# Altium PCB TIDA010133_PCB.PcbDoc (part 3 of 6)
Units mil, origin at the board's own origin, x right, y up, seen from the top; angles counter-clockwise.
Board outline 4100 x 6400 mil, 8 copper layers (Top Layer, Ground 1, Signal 1, Power 1, Ground 2, Signal 2, Power 2, Bottom Layer), stack 60.4 mil thick; 587 components, 322 nets, 1661 pads, 859 vias.
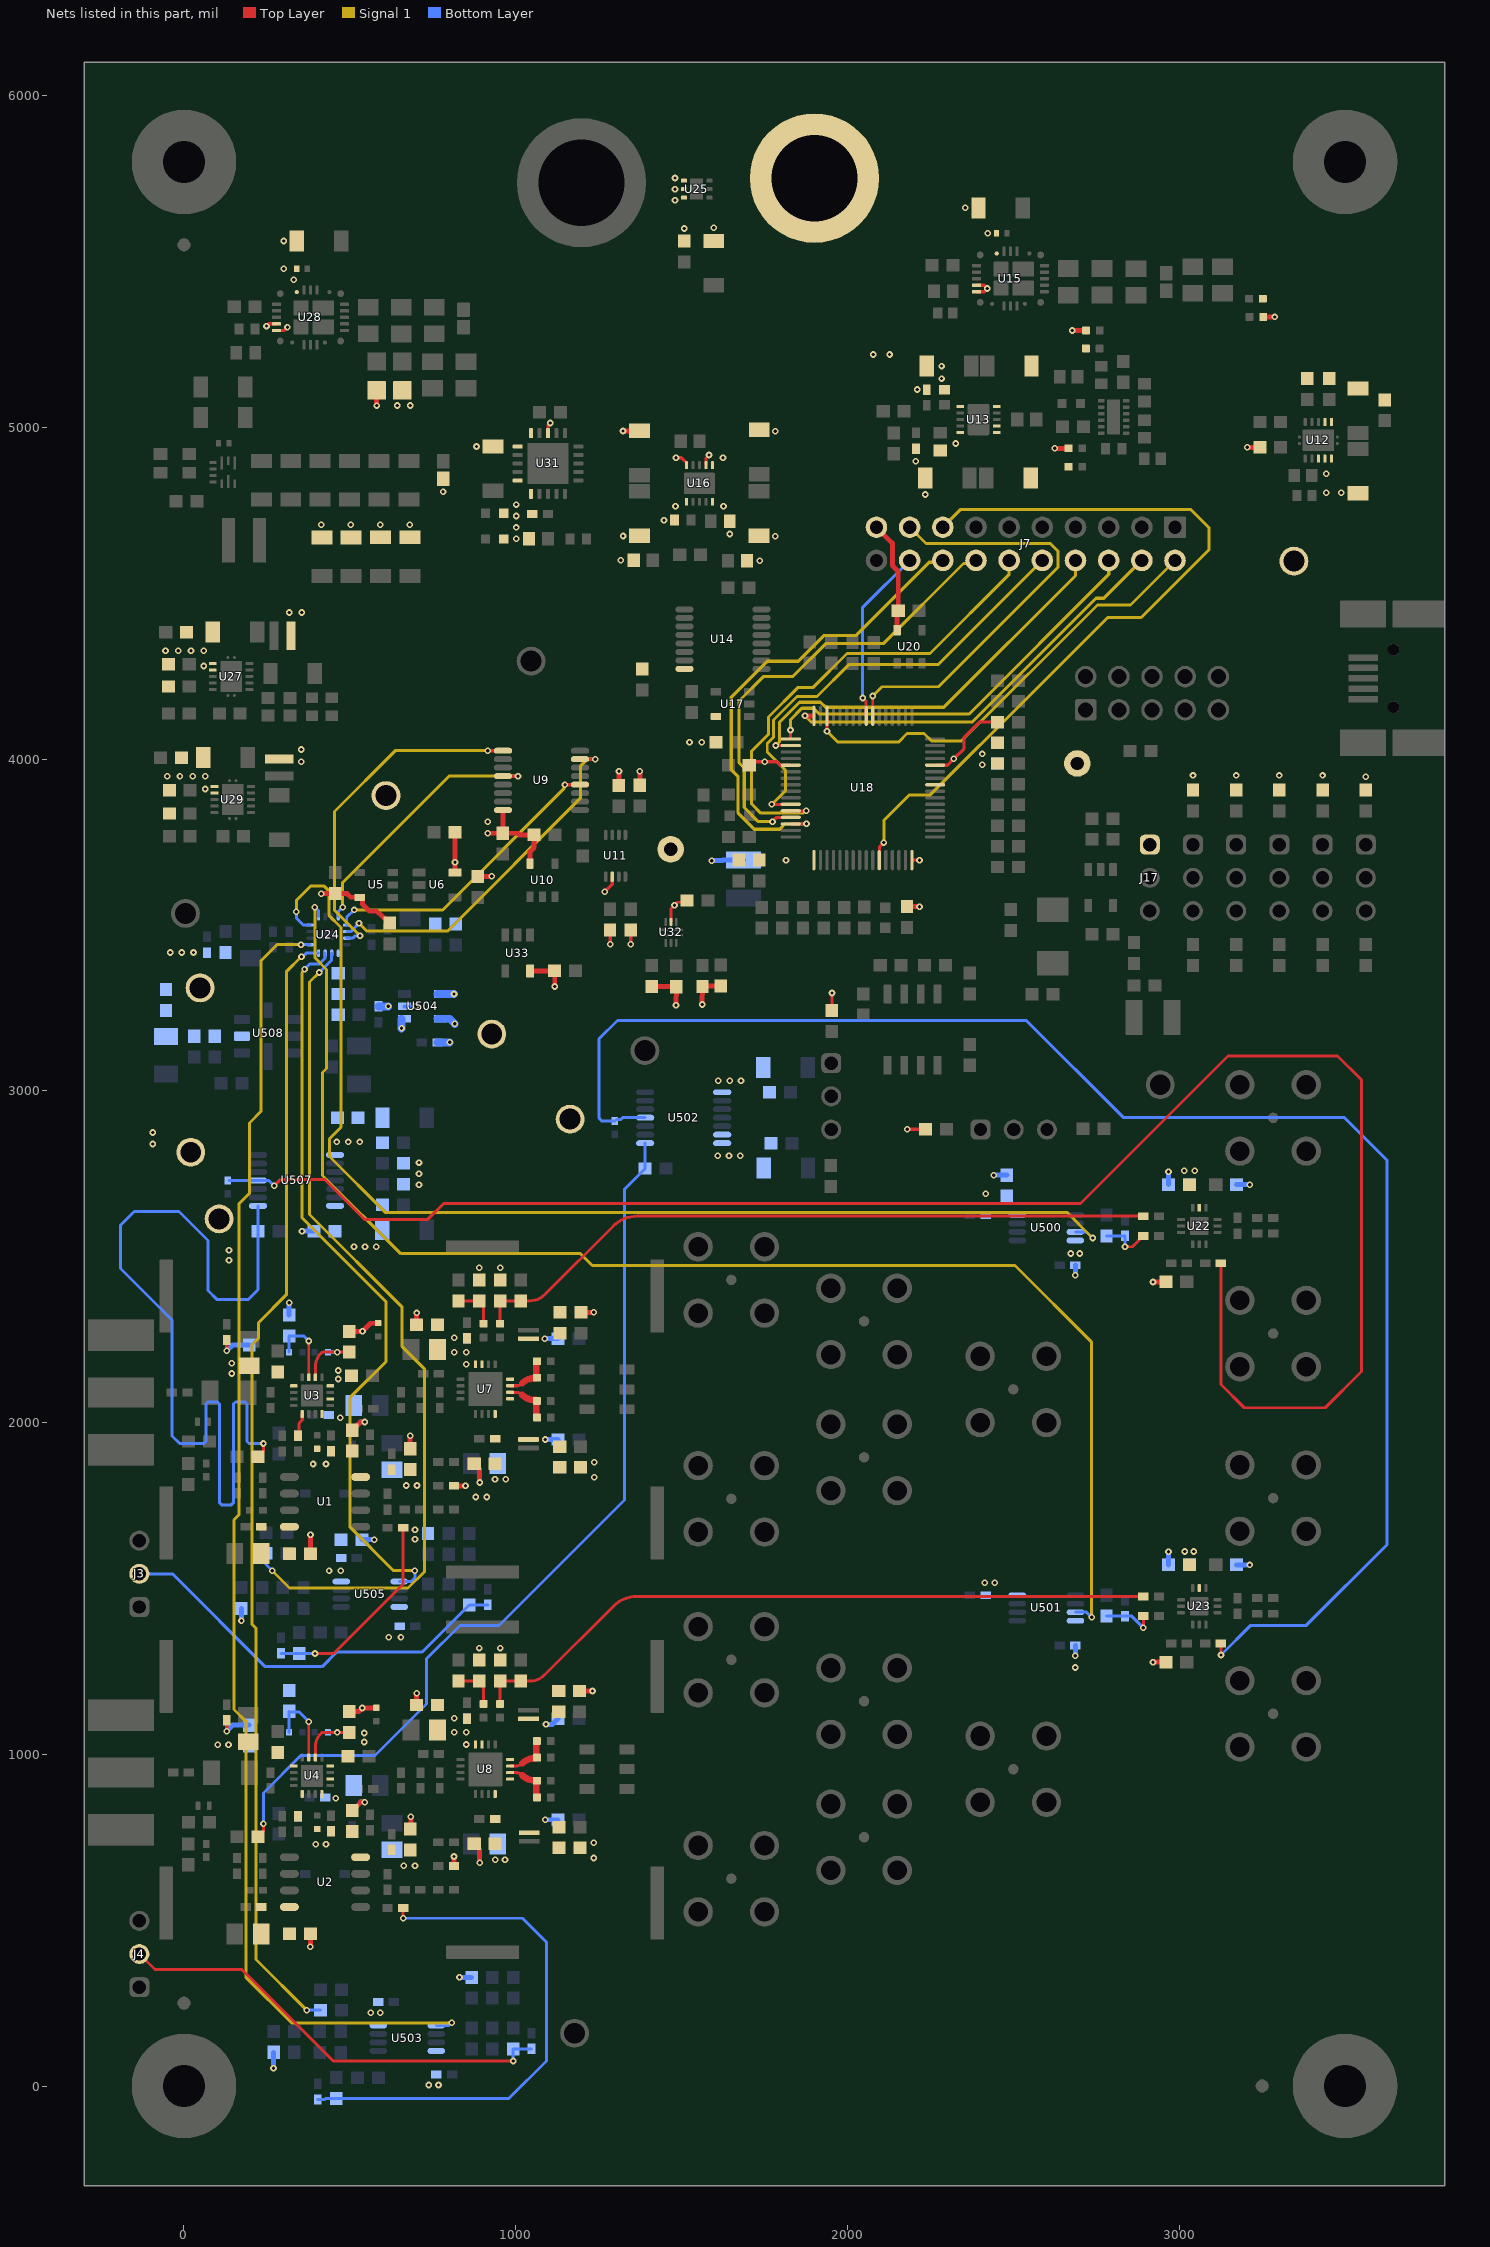
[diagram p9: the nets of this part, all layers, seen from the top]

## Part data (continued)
R101 R167: library part CMP-0090334-1, "6 mOhms ±1% 1W Chip Resistor Wide 0805 (2012 Metric), 0508 Automotive AEC-Q200, Current Sense Metal Foil", Digikey Part Number=408-1596-1-ND, Manufacturer=Susumu, Mouser Part Number=754-KRL2012EMR006FT5, Operating Temperature Range="-55°C to +155°C", Power_W=660mW, TempCo=50ppm/°C, Tolerance_%=1%
R103: library part CMP-2000-00576-1, "57.6 kOhms ±1% 0.1W, 1/10W Chip Resistor 0603 (1608 Metric) Automotive AEC-Q200 Thick Film", Manufacturer=Panasonic
R108: library part CMP-1012-00672-2, "28 kOhms ±1% 0.1W, 1/10W Chip Resistor 0603 (1608 Metric) Automotive AEC-Q200 Thick Film", Manufacturer=Panasonic
R110 R134: library part CMP-0025765-4, "RES, 270, 5%, 0.1 W, AEC-Q200 Grade 0, 0603", Manufacturer=Vishay-Dale, Power_W=100mW, Supplier Part Number 1=541-270GCT-ND, TempCo="200 ppm/C", Tolerance_%=5%, Value2=0.1W, Value_Code=270R, ValueDisplayed=270
R113 R114: library part CMP-0096818-1, "0 Ohms Jumper 0.245W Chip Resistor 0805 (2012 Metric) - Metal Element", Digikey Part Number=JR0805X35ECT-ND, Manufacturer=Ohmite, Mouser Part Number=588-JR0805X35E, Operating Temperature Range="-55°C to +150°C", Power_W=245mW
R116 R117: library part CMP-2000-00441-1, "33.2 kOhms ±1% 0.1W, 1/10W Chip Resistor 0603 (1608 Metric) Automotive AEC-Q200 Thick Film", Manufacturer=Panasonic
R133: library part CMP-0025769-4, "RES, 2.2 k, 5%, 0.1 W, AEC-Q200 Grade 0, 0603", Manufacturer=Vishay-Dale, Power_W=100mW, Supplier Part Number 1=541-2.2KGCT-ND, TempCo="200 ppm/C", Tolerance_%=5%, Value2=0.1W, Value_Code=2k20, ValueDisplayed=2.2k
R137 R138: library part CMP-0022004-4, "RES, 10.0, 1%, 0.25 W, AEC-Q200 Grade 0, 0603", Manufacturer=Vishay-Dale, Power_W=250mW, Supplier Part Number 1=541-10.0SCT-ND, TempCo="100 ppm/C", Tolerance_%=1%, Value2=0.25W, Value_Code=10R0, ValueDisplayed=10.0
R139: library part CMP-0025711-4, "RES, 12 k, 5%, 0.1 W, AEC-Q200 Grade 0, 0603", Manufacturer=Vishay-Dale, Power_W=100mW, Supplier Part Number 1=541-12KGCT-ND, TempCo="200 ppm/C", Tolerance_%=5%, Value2=0.1W, Value_Code=12k0, ValueDisplayed=12k
R140: library part CMP-0022109-5, "RES, 1.00 k, 1%, 0.1 W, AEC-Q200 Grade 0, 0603", Manufacturer=Vishay-Dale, Power_W=100mW, Supplier Part Number 1=541-1.00KHCT-ND, TempCo="100 ppm/C", Tolerance_%=1%, Value2=0.1W, Value_Code=1k00, ValueDisplayed=1.00k
R143 R144 R145 R146 R154 R155: library part CMP-0026822-3, "RES, 0, 5%, 0.063 W, AEC-Q200 Grade 0, 0402", Manufacturer=Vishay-Dale, Power_W=63mW, Supplier Part Number 1=541-0.0JCT-ND, TempCo="200 ppm/C", Tolerance_%=5%, Value2=0.063W, Value_Code=0000, ValueDisplayed=0
R149 R150: library part CMP-0026822-3, "RES, 0, 5%, 0.063 W, AEC-Q200 Grade 0, 0402", Manufacturer=Vishay-Dale, Power_W=63mW, Supplier Part Number 1=541-0.0JCT-ND, TempCo="200 ppm/C", Tolerance_%=5%, Value2=0.063W, Value_Code=0000, ValueDisplayed="0 (DNP)"
R169: library part CMP-1012-00667-2, "25.5 kOhms ±1% 0.1W, 1/10W Chip Resistor 0603 (1608 Metric) Automotive AEC-Q200 Thick Film", Manufacturer=Panasonic
R175: library part CMP-2000-00404-1, "28.7 kOhms ±1% 0.1W, 1/10W Chip Resistor 0603 (1608 Metric) Automotive AEC-Q200 Thick Film", Manufacturer=Panasonic
R177: library part CMP-2000-00442-1, "332 kOhms ±1% 0.1W, 1/10W Chip Resistor 0603 (1608 Metric) Automotive AEC-Q200 Thick Film", Manufacturer=Panasonic
R179: library part CMP-1012-00737-2, "102 kOhms ±1% 0.1W, 1/10W Chip Resistor 0603 (1608 Metric) Automotive AEC-Q200 Thick Film", Manufacturer=Panasonic
R500 R501 R517 R518 R520 R521 R522 R523 R525 R526 R535 R538 R541 R542 R547 R549 R550 R554: library part CMP-0022895-5, "RES, 1.00 k, 1%, 0.1 W, 0603", Manufacturer=Yageo, Power_W=100mW, Supplier Part Number 1=311-1.00KHRCT-ND, TempCo="100 ppm/C", Tolerance_%=1%, Value2=0.1W, Value_Code=1k00, ValueDisplayed=1.00k
R508 R532 R548 R553: library part CMP-0025697-4, "RES, 0, 5%, 0.1 W, AEC-Q200 Grade 0, 0603", Manufacturer=Vishay-Dale, Power_W=100mW, Supplier Part Number 1=541-0.0GCT-ND, TempCo="200 ppm/C", Tolerance_%=5%, Value2=0.1W, Value_Code=0000, ValueDisplayed="0 (DNP)"
R511 R555: library part CMP-0026003-3, "RES, 13.0 k, 1%, 0.063 W, AEC-Q200 Grade 0, 0402", Manufacturer=Vishay-Dale, Power_W=63mW, Supplier Part Number 1=541-13.0KLCT-ND, TempCo="100 ppm/C", Tolerance_%=1%, Value2=0.063W, Value_Code=13k0, ValueDisplayed="13.0k (DNP)"
R513 R514 R515 R516: library part CMP-0022871-5, "RES, 1.21 k, 1%, 0.1 W, 0603", Manufacturer=Yageo, Power_W=100mW, Supplier Part Number 1=311-1.21KHRCT-ND, TempCo="100 ppm/C", Tolerance_%=1%, Value2=0.1W, Value_Code=1k21, ValueDisplayed=1.21k
R519 R524 R529 R534: library part CMP-0023343-3, "RES, 0, 1%, 0.1 W, AEC-Q200 Grade 0, 0603", Manufacturer="Stackpole Electronics Inc", Power_W=100mW, Supplier Part Number 1=RMCF0603ZT0R00CT-ND, TempCo=ppm/C, Tolerance_%=1%, Value2=0.1W, Value_Code=0
R551 R552: library part CMP-0026158-2, "RES, 200 k, 1%, 0.063 W, AEC-Q200 Grade 0, 0402", Manufacturer=Vishay-Dale, Power_W=63mW, Supplier Part Number 1=541-200KLCT-ND, TempCo="100 ppm/C", Tolerance_%=1%, Value2=0.063W, Value_Code=200k
T1 T2: library part CMP-0087429-1, "Wideband RF transformer, SMT, RoHS", Manufacturer=Coilcraft
TP1 TP8 TP9 TP11 TP13: library part CMP-0055148-2, "Test Point, Multipurpose, Black, TH", Color=Black, Manufacturer="Keystone Electronics", Supplier Part Number 1=36-5011-ND
TP2 TP3 TP4 TP5 TP6 TP7 TP14: library part CMP-0055147-2, "Test Point, Multipurpose, Red, TH", Color=Red, Manufacturer="Keystone Electronics", Supplier Part Number 1=36-5010-ND
TP10 TP12: library part CMP-0055137-2, "Test Point, Miniature, Red, TH", Color=Red, Manufacturer="Keystone Electronics", Supplier Part Number 1=36-5000-ND
U1 U2: library part CMP-0040579-1, "11 MHz, Precision, Low Noise, Rail-to-Rail Output, JFET Operational Amplifier, 4.5 to 36 V, -40 to 125 degC, 8-pin SOIC (D8), Green (RoHS & no Sb/Br)", Manufacturer="Texas Instruments", Rating=Catalog, Total Supply Voltage(Max)(+5V is 5, +/-5V is 10)=36, Total Supply Voltage(Min)(+5V is 5, +/-5V is 10)=4.5
U3 U4: library part CMP-0090241-1, Manufacturer="Texas Instruments", Operating Temperature Range=to
U5 U10 U17 U20: library part CMP-0051300-2, "Single Bus Buffer Gate With 3-State Outputs, DBV0005A, LARGE T&R", Alternate Manufacturer="Texas Instruments", F @ Nom Voltage(Max)(Mhz)=150, Generic Part Number=SN74LVC1G125, ICC @ Nom Voltage(Max)(mA)=0.01, Operating Temperature Range(C)="-40 to 125,-40 to 85", Rating=Catalog, tpd @ Nom Voltage(Max)(ns)=9,5.5,4.5,4, Voltage(Nom)(V)=1.8,2.5,3.3,5
U6 U33: library part CMP-0052003-3, "Single Bus Buffer Gate With 3-State Outputs, DBV0005A (SOT-23-5)", F @ Nom Voltage(Max)(Mhz)=150, Generic Part Number=SN74LVC1G126, ICC @ Nom Voltage(Max)(mA)=0.01, Manufacturer="Texas Instruments", Operating Temperature Range="-40 to 125 C", Rating=Catalog, tpd @ Nom Voltage(Max)(ns)=8,5.5,4.5,4, Voltage(Nom)(V)=1.8,2.5,3.3,5
U7 U8: library part CMP-0092895-1, "Variable Gain Amplifier 1 Circuit Differential 16-WQFN (4x4)", Digikey Part Number=296-LMH6518SQ/NOPBCT-ND, Manufacturer="Texas Instruments", Max Supply Voltage=5.25V, Min Supply Voltage=3.135V, Mouser Part Number=926-LMH6518SQ/NOPB, Nominal Supply Current=150-210mA, Operating Temperature Range="-40°C to +85°C", Voltage Gain=38.8dB
U9 U14: library part CMP-0086166-2, "Low-capacitance, 2:1 (SPDT) 4-channel, powered-off protection switch with 1.8 V logic, PW0016A (TSSOP-16)", Alternate Manufacturer="Texas Instruments", Operating Temperature Range="-40 to 125 C", Rating=Catalog
U11: library part CMP-0066433-2, "Dual Bidirectional Multi-Voltage Level Translator, DCU0008A (VSSOP-8)", Alternate Manufacturer="Texas Instruments", Operating Temperature Range="-40 to 125 C", Rating=Catalog
U12 U27 U29: library part CMP-0091022-1, "1-A, Ultra-Low Noise, Ultra-High PSRR, RF Voltage Regulator", Dropout Voltage=210mV, Manufacturer="Texas Instruments", Max Supply Voltage=5.5V, Min Supply Voltage=1.7V, Nominal Supply Current=15-47mA, Operating Temperature Range="-40°C to +150°C", Output Voltage=0.4-5.3V
U13 U16: library part CMP-0013435-7, "Dual, 150mA, Wide-Vin, Positive and Negative Low-Dropout (LDO) Voltage Regulator, DSC0010J (WSON-10)", Alternate Manufacturer="Texas Instruments", Alternate PartNumber=TPS7A3901DSCT, Operating Temperature Range="-40 to 125 C", Rating=Catalog
U15 U28: library part CMP-0094707-3, "3-V to 17-V, 3-A Low Noise and Low Ripple Buck Converter Module with Integrated Ferrite Bead Filter Compensation", Manufacturer="Texas Instruments", Max Supply Voltage=17V, Min Supply Voltage=3V, Nominal Supply Current=5mA, Operating Temperature Range="-55°C to +125°C", Output Voltage=0.8-5.5V, Switching Frequency=1/2.2MHz
U18: library part CMP-0004747-1, "Quad High Speed USB to Multipurpose UART/MPSSE IC", Manufacturer=FTDI, Supplier Part Number 1=768-1026-1-ND
U19: library part CMP-0005249-2, "1K Microwire Compatible Serial EEPROM", Manufacturer=Microchip, Supplier Part Number 1=93LC46BT-I/SNCT-ND
U21: library part CMP-0035516-1, "Single Output LDO, 300 mA, Fixed 3.3 V Output, 2 to 5.5 V Input, with Low IQ, 5-pin SOT-23 (DBV), -40 to 125 degC, Green (RoHS & no Sb/Br)", Manufacturer="Texas Instruments"
U22 U23: library part CMP-0860887-1, "1ns High-Speed Comparator with LVDS Outputs, RVK0012A (QFN-12)", Alternate Manufacturer="Texas Instruments"
U24: library part CMP-0084837-1, "8-Channel, True 16-Bit, SPI, Voltage-Output DAC With Precision Internal Reference, RTE0016D (WQFN-16)", Alternate Manufacturer="Texas Instruments", Alternate PartNumber=DAC80508MRTER, Operating Temperature Range="-40 to 125 C", Rating=Catalog
U25: library part CMP-0077836-1, "14-V Precision Surge Protection Clamp, DRV0006A (WSON-6)", Alternate Manufacturer="Texas Instruments"
U26: library part CMP-0076280-3, "Low-Noise Positive- and Negative-Output Charge Pump With Integrated LDO, DSS0012B (WSON-12)", Alternate Manufacturer="Texas Instruments", Alternate PartNumber=LM27762DSST, Operating Temperature Range="-40 to 85 C", Rating=Catalog
U30: library part CMP-0089785-1, "3V to 17V, 3A Micro Noise (20µVRMS) and Micro Ripple (200µVPP) buck converter", Manufacturer="Texas Instruments", Max Supply Voltage=17V, Min Supply Voltage=3V, Nominal Supply Current=5mA, Operating Temperature Range="-40°C to +150°C", Output Voltage=0.8-5.5V, Switching Frequency=1/2.2MHz
U31: library part CMP-0036411-3, "Vin -3V to -36V, -1A, Ultra-Low-Noise, High-PSRR, Low-Dropout Linear Regulator, RGW0020A (VQFN-20)", Manufacturer="Texas Instruments", Operating Temperature Range="-40 to 125 C", Rating=Catalog
U32: library part CMP-0122684-1, "2-pF, 3.3-V, 2:1 (SPDT), 2-channel, switch with 1.8-V compatible logic", Digikey Part Number=296-TMUX121NKGRCT-ND, Manufacturer="Texas Instruments", Max Supply Voltage=3.6V, Min Supply Voltage=3V, Mouser Part Number=595-TMUX121NKGR, Nominal Supply Current=1.3-11uA, On State Resistance=3.9Ω, Operating Temperature Range="-40°C to +125°C"
U500 U501 U503 U505: library part CMP-0040605-2, "0.03µV/°C, 6µV Vos, Low Noise, Rail-to-Rail Output, 36V Zero-Drift Operational Amplifier, DGK0008A (VSSOP-8)", Manufacturer="Texas Instruments", Rating=Catalog, Total Supply Voltage(Max)(+5V is 5, +/-5V is 10)=36, Total Supply Voltage(Min)(+5V is 5, +/-5V is 10)=4
U502 U507: library part CMP-0066591-1, "256-Taps Dual-Channel Digital Potentiometer With I2C Interface and Nonvolatile Memory, PW0014A (TSSOP-14)", Alternate Manufacturer="Texas Instruments"
U504: library part CMP-0860961-1, "14MHz, MUX-friendly, low-noise, zero-drift, RRO, CMOS precision operational amplifier, DBV0005A (SOT-23-5)", Alternate Manufacturer="Texas Instruments", Alternate PartNumber=OPA189IDBVT, Operating Temperature Range="-40 to 125 C", Rating=Catalog
U508: library part CMP-0091880-1, "2 ppm/°C Maximum Drift, 0.23 ppmp-p 1/f Noise, Precision Voltage Reference", Manufacturer="Texas Instruments", Max Supply Voltage=18V, Min Supply Voltage=3V, Nominal Supply Current=4mA, Operating Temperature Range="-40°C to +125°C", Output Voltage=2.5V
Y1: library part CMP-0004616-3, "Crystal, 12 MHz, 18 pF, SMD", Frequency Stability=+/-30ppm, Frequency_Fixed=12MHz, Manufacturer="Abracon Corporation", Supplier Part Number 1=535-10634-1-ND
ZZ1: library part CMP-0077237-1
ZZ2: library part CMP-0077238-1
ZZ3: library part CMP-0077238-1, "These assemblies must comply with workmanship standards IPC-A-610 Class 2, unless otherwise specified."
ZZ4: library part CMP-0003616-3
ZZ5: library part CMP-0077236-1

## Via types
v1: diameter 20, hole 10, Top Layer to Bottom Layer, tented top, 776 vias
v2: diameter 19.68, hole 7.87, Top Layer to Bottom Layer, tented bottom, 82 vias
v3: diameter 19.68, hole 7.87, Top Layer to Bottom Layer, 1 vias

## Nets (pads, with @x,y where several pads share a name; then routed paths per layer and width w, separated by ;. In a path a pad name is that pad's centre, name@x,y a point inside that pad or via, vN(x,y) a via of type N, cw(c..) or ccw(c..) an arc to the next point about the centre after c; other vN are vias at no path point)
1P8V_USB: C65.2 C70.1 C76.2 C88.2 C514.1 TP10.1 U18.12 U18.37 U18.49 U18.64 | length 515.3
  Top Layer w9: U18.64@2194.37,3695.4 v1(2217.24,3695.4)
  Top Layer w9.84: C65.2@1704.02,3981.82 1714.25,3992.05 v1(1750.95,3992.05) 1787.66,3992.05 1797.89,3981.82 U18.37@1829.21,3981.82 ; U18.12@2264.25,3981.82 2301.62,3981.82 v1@2321.02,4001.22 ; v1(2320.85,4001.05) 2351.59,4031.79 2351.59,4065.97 2397.26,4111.64 C88.2@2452.43,4111.64
  Bottom Layer w15: v1(1590.99,3693.66) 1622.71,3693.66 1624.46,3695.4 C514.1@1686.77,3695.4
  other v1: 1814.96,3695.4
2.5V_DACREF: C549.1 R532.1 R533.2 U24.1
2.5V_DACREF1: R521.1 R526.1 R549.1 R554.1 U504.1 U504.4 | length 200.7
  Bottom Layer w15: v1(173.09,1402.7) R554.1@173.09,1439.38 ; v1(270.01,53.17) R549.1@270.03,101.73 ; v1(830.61,327.69) R521.1@867.3,327.69
  Bottom Layer w23.62: v1(655.88,3188.35) U504.1@655.88,3217.16 ; U504.4@764.14,3291.96 v1(814.13,3291.96)
  other v1: 696.39,1648.29 696.39,1676.37
3P3USB: C87.2 C504.1 L21.2 TP12.1 U18.9
  other v1: 2405.89,3982.52 2405.89,4015.61
+2.5VA: C25.1 C26.1 L512.1 R83.2 R86.2 TP4.1 U13.10 U16.2 U28.24 | length 146.5
  Top Layer w9.45: U16.2@1573.69,4886.12 1573.69,4907.8 v1(1582.54,4916.66)
  Top Layer w9.84: U28.24@278.94,5292.38 302.03,5292.38 v1(311.8,5302.15)
  Top Layer w15: v1(2625.04,4937) R86.2@2663.76,4937
  Bottom Layer w15: v1(355.7,2576.82) L512.1@392.4,2576.82
  other v1: 135.52,2489.61 135.52,2519.51 2234.07,4797.5 2206.33,4897.5 2326.31,4951.22
+2.5VA_1: C511.2 C513.1 C535.2 C539.1 L512.2 R93.2 R95.2 R527.2 R528.2 U11.2 U502.13 U502.14 U507.14 | length 140
  Top Layer w10: v1(1268.35,3599.82) 1290.72,3622.19 U11.2@1290.72,3645.11 ; R93.2@1284.19,3484.32 1284.69,3483.82 v1(1284.69,3441.84) ; R95.2@1346.59,3484.32 1347.1,3483.82 v1(1347.1,3441.84)
  other v1: 512.32,2529.78 545.81,2529.78 579.28,2529.78 708.62,2716.72 708.62,2750.22 708.62,2783.69 1609.43,2804.29 1642.91,2804.29 1676.4,2804.29
+3.8V_IN_TPS7A94: C21.1 R68.1 R69.1 R70.2 R78.2 U12.1 U12.2
+3P3VD: C14.1 C17.1 C41.1 C54.1 C55.1 C56.1 C58.1 C64.2 C84.2 C530.1 J7.19 J17.1 L13.1 L14.1 L500.2 L501.2 L509.1 R23.2 R28.2 R29.2 R50.2 R55.2 R62.2 R65.2 R66.2 R67.2 R71.1 R79.2 R94.2 R96.2 R134.2 R147.1 R148.1 R152.2 R156.2 R162.2 R164.2 R165.2 TP14.1 U5.5 U6.5 U9.16 U10.5 U12.8 U12.9 U12.10 U14.16 U17.5 U20.5 U32.9 U33.5 | length 2092.8
  Top Layer w8: U32.9@1468.15,3508.93 1468.15,3548.72 ; 1469.7,3550.27 1487.54,3568.1 C17.1@1510.7,3568.1
  Top Layer w10: C17.1@1510.7,3568.1 C17.1@1516.36,3573.76 ; R28.2@1952.27,3242.27 1953.46,3243.45 v1(1953.46,3294.83) ; v1(2180.14,2884.36) 2235.18,2884.36 R29.2@2235.37,2884.55
  Top Layer w15: v1@413.95,3594.94 R23.2@455.93,3594.94 491.1,3594.94 502.48,3583.56 U5.5@528.88,3583.56 ; U5.5@529.31,3583.13 534.23,3583.13 537.56,3579.8 537.56,3563.15 559.32,3541.38 581.36,3541.38 619.72,3506.34 C56.1@619.72,3505.36 ; v1(816.98,3689.19) C58.1@816.99,3779.11 ; U6.5@817.11,3657.93 v1@817.11,3689.06 ; L14.1@874.91,729.88 891.24,713.56 v1(891.24,672.91) ; L13.1@874.91,1876.14 891.24,1859.81 v1(891.24,1819.16) ; R50.2@885.22,3646.12 v1@927.2,3646.12 ; v1(915.99,3776.44) C41.1@961.5,3776.44 ; U9.16@961.56,3846.27 961.5,3846.27 C41.1@961.5,3776.44 ; U33.5@1043.18,3361.2 1043.32,3361.34 1117.14,3361.34 C54.1@1117.27,3361.48 1117.62,3361.13 1117.62,3315.05 v1(1117.97,3314.7) ; U10.5@1043.32,3685.16 1043.32,3720.93 1055.13,3732.74 R62.2@1055.13,3771.44 1012.1,3771.44 1007.1,3776.44 C41.1@961.5,3776.44 ; R94.2@1311.91,3921.25 v1@1311.91,3963.23 ; R96.2@1374.31,3921.24 v1@1374.31,3963.23 ; R66.2@1410.08,3314.54 R66.2@1410.3,3314.32 ; R66.2@1419.14,3315.02 1419.3,3315.18 1480.65,3315.18 R65.2@1480.81,3315.33 ; v1(1483.34,3257.82) 1483.14,3258.02 R65.2@1484,3313.55 ; R67.2@1555.69,3315.64 1556.33,3316.27 1618.3,3316.27 R55.2@1618.56,3316.54 ; v1(1562.62,3260.36) 1562.25,3260.73 R67.2@1563.09,3314.91 ; J7.19@2087.47,4699 2135.33,4651.15 2135.33,4583.47 2153.17,4565.63 C84.2@2153.17,4447.41 2150.08,4444.32 U20.5@2150.08,4388.78 ; R134.2@2179.49,3555.2 v1(2217.17,3555.2) ; v1(2921.07,1277.59) R148.1@2959.77,1277.59 ; v1(2921.07,2423.85) R147.1@2959.77,2423.85 ; v1(3205.32,4940) R71.1@3243.01,4940 ; R79.2@3256.24,5332.98 v1(3288.02,5332.98)
  Bottom Layer w15: L501.2@3173.34,1570.84 v1(3213.04,1570.84) ; L500.2@3173.34,2717.1 v1(3213.04,2717.1)
  other v1: 879.87,1775.51 912.53,1775.51 1478.62,3559.18 413.44,3594.43 927.71,3646.63 915.99,3811.52 3562.51,3946.85 3041.57,3950.84 3171.8,3950.84 3302.04,3950.84 3432.28,3950.84 1311.41,3963.73 1373.81,3963.73 1524.04,4050.71 1560.99,4050.71 3443.48,4802.59 3488.31,4802.59 3443.48,4860.28
+3P3VD_LMH6518_1: C39.1 C525.1 L13.2 U7.12
  other v1: 937.55,1829.06 969.68,1829.06
+3P3VD_LMH6518_2: C40.1 C524.1 L14.2 U8.12
  other v1: 938.46,681.93 967.86,681.93
+3V_INP_TPS7A39: C35.1 R88.2 U13.1 U13.2
+5.5V_IN_TPS7A94: C124.1 C136.1 R102.1 R104.1 R106.2 R113.2 R168.1 R170.1 R172.2 U27.1 U27.2 U29.1 U29.2 | length 46
  Top Layer w15: v1(581,5065.72) R113.2@581,5111.69
  other v1: 64.47,3909.86 -50.72,3948.26 -12.32,3948.26 26.07,3948.26 64.47,3948.26 59.47,4280.86 -55.72,4326.26 -17.32,4326.26 21.07,4326.26 59.47,4326.26
+5VA: C532.1 C567.1 L9.2 L10.2 L11.1 L12.2 L502.1 L503.1 L504.1 L515.1 L516.2 R43.2 R45.2 R101.2 R114.2 R167.2 TP3.1 | length 363
  Top Layer w15: L9.2@681.95,1921.07 v1(681.95,1959.75) ; L10.2@683.64,776.51 v1(683.64,811.32) ; L12.2@701.24,1148.57 v1(701.24,1184.27) ; L11.1@701.24,2294.82 v1(701.24,2330.52) ; R45.2@813.97,663.05 v1(813.97,691.86) ; R43.2@813.97,1809.31 v1(848.72,1809.31)
  Bottom Layer w15: v1(2441.49,2745.57) L504.1@2480.77,2745.57 ; L503.1@2967.67,1570.84 v1(2967.67,1610.12) ; L502.1@2967.67,2717.1 v1(2967.67,2756.37)
  Bottom Layer w23.62: C532.1@764.14,3146.18 v1(800.83,3146.18)
  other v1: -41.69,3417.01 -6.47,3417.01 28.74,3417.01 353.23,3992 353.23,4029.13 317.47,4442.02 354.61,4442.02 642.44,5065.95 682.13,5065.95
+5VA_C: C506.1 C507.1 C531.1 C537.1 L504.2 U500.8 U501.8 U503.8 U504.5 U505.8 | length 58.2
  Bottom Layer w23.62: U504.5@764.14,3217.16 800.83,3217.16 v1(816.04,3201.95)
  other v1: 737.8,3.11 767.2,3.11 616.89,1353.24 653.91,1353.24 2413.79,1517.2 2444.43,1517.2 2416.45,2690.01
+5VA_LMH6518_1: C29.1 C36.1 C529.1 L11.2 R51.2 R56.2 R72.2 R73.2 U7.3 U7.4 | length 38.7
  Top Layer w15: R72.2@1196.2,2332.19 v1(1234.88,2332.19)
  other v1: 1237.15,1834.75 1237.15,1880.13 850.86,2175.59 814.26,2212.18 850.86,2212.18 814.26,2255.2 889.99,2466.41 952.9,2466.41
+5VA_LMH6518_2: C30.1 C37.1 C528.1 L12.1 R52.2 R57.2 R74.2 R75.2 U8.3 U8.4 | length 38.7
  Top Layer w15: R74.2@1192.61,1190.88 v1(1231.3,1190.88)
  other v1: 1234.99,687.52 1234.99,732.9 850.86,1029.33 814.26,1065.93 850.86,1065.93 814.26,1108.94 889.99,1320.15 952.9,1320.15
+5VA_OPA140_1: C27.2 C540.2 L9.1 U1.8
  other v1: 669.91,1810.36 702.57,1810.36
+5VA_OPA140_2: C28.2 C541.2 L10.1 U2.8
  other v1: 662.26,663.68 696.35,663.68
+5VA_REF7025_1: C568.1 C569.1 L516.1 R556.2 U508.2
+5VA_TLV3605_1: C96.2 L502.2 U22.2
  other v1: 3015.54,2759.51 3046.94,2759.51
+5VA_TLV3605_2: C97.2 L503.2 U23.2
  other v1: 3016.69,1611.36 3044.28,1611.36
+8VA: C1.1 C2.1 C69.2 C71.1 L513.2 L514.2 R103.2 TP5.1 U16.10 | length 216.1
  Top Layer w9.45: v1(128.74,1069.83) C2.1@128.74,1102.58 ; v1(128.74,2216.09) C1.1@128.74,2248.84
  Bottom Layer w15: v1(128.74,1069.83) 146.49,1087.58 L513.2@196.69,1087.58 ; v1(128.74,2216.09) 146.49,2233.84 L514.2@196.69,2233.84
  other v1: 1735.8,4598 1782.63,4671.47 1645.22,4678.65 1626.27,4762.2
+8VA_BUF802_1: C7.1 C15.1 C24.1 L514.1 R545.2 U3.1 U3.12 | length 36.7
  Bottom Layer w15: R545.2@317.19,2324.5 v1(317.2,2361.17)
  other v1: 464.79,2131.39 143.94,2147.93 464.79,2156.76 143.94,2179.15
+8VA_BUF802_2: C8.1 C16.1 C23.1 L513.1 R546.2 U4.1 U4.12
  other v1: 101.32,1028.63 134.04,1028.63 543.33,1036.81 543.33,1064.14
+12VA: C13.2 C57.1 C61.1 C68.1 C104.2 C105.1 C109.1 J5.1 U15.18 U15.23 U15.24 U16.1 U25.4 U25.5 U25.6 U28.18 U28.23 | length 106.9
  Top Layer w9.84: v1(248.63,5305.4) 255.29,5312.06 U28.23@278.94,5312.06 ; U15.24@2388.98,5408.88 2412.07,5408.88 v1(2421.84,5418.65) 2411.92,5428.57 U15.23@2388.98,5428.57
  other v1: 1624.94,4908.47 1782.77,4987.96 331.01,5444.82 300.31,5478.09 300.31,5562 2423.38,5585 1508,5599.68 1597,5601.65 2355.25,5661.92 1480.09,5684.67 1480.21,5718.18 1480.09,5751.68
-2.5VA: C38.1 C43.1 L511.2 R87.2 R100.2 TP2.1 U13.6 | length 38.7
  Top Layer w15: v1(2677.67,5292.03) R100.2@2716.38,5292.03
  other v1: -94.49,2839.85 -94.49,2874.29 2210.75,5114.38 2283.78,5147.13 2283.78,5184.81 2077.32,5219.49 2126.98,5219.49
-2.5VA_1: C510.2 C512.1 C534.2 C538.1 L511.1 U502.8 U507.8
  other v1: 460.76,2845.96 495.16,2845.96 529.56,2845.96 1610.39,3030.08 1644.79,3030.08 1679.19,3030.08
-3.3VA: C77.2 C79.1 C551.2 C552.2 L7.1 L8.1 R108.2 TP7.1 U16.6 | length 190
  Top Layer w15: L8.1@507.45,830.5 532.4,855.46 v1(544.62,855.46) ; L7.1@507.45,1976.75 532.4,2001.71 v1(544.62,2001.71)
  Bottom Layer w15: C552.2@507.45,830.5 532.4,855.46 v1(544.62,855.46) ; C551.2@507.45,1976.75 532.4,2001.71 v1(544.62,2001.71)
  other v1: 1316.88,4599.71 1323.64,4672.57 1447.14,4720.37 1481.73,4762.2
-3.3VA_BUF802_1: C19.1 C545.1 C556.1 C559.1 L7.2 R19.2 R21.1 R24.2 R180.2 U3.5 U3.8 U3.10 | length 168.7
  Top Layer w9.45: C19.1@343.72,1959.91 346.48,1962.66 346.48,1997.6 356.48,2007.6 U3.5@356.48,2026.13
  Top Layer w15: R24.2@497.86,2275.11 v1(537.92,2275.11) 562.18,2299.37 R180.2@585,2299.37
  other v1: 389.09,1875.06 428.24,1875.06 471.15,2014.83
-3.3VA_BUF802_2: C20.1 C544.1 C555.1 C560.1 L8.2 R20.2 R22.1 R25.2 R181.2 U4.5 U4.8 U4.10 | length 86.6
  Top Layer w15: R25.2@497.86,1128.86 526.4,1128.86 v1(537.23,1139.69) R181.2@580,1139.69
  other v1: 397.57,728.81 428.24,728.81 457.76,867.41
-3V_INN_TPS7A39: C42.1 R92.2 U13.5
-5.5V_IN_TPS7A33: C130.1 C137.1 C138.1 C139.1 C140.1 FB3.2 U31.13 U31.15 U31.16 | length 33.4
  Top Layer w10: U31.13@1097.32,4982.65 1097.32,5005.97 v1(1104.46,5013.11)
  other v1: 414.07,4706.55 502.75,4706.55 591.78,4706.55 680.47,4706.55 781,4806.29 881.9,4942.3
-5VA: C78.1 C129.1 C131.2 C135.2 C546.1 L3.2 L4.2 L510.1 R177.2 TP6.1 U16.5 U31.1 U31.20 | length 256.5
  Top Layer w9.45: v1(1483.06,4908.47) 1499.37,4908.47 1514.63,4893.2 U16.5@1514.63,4886.12
  Top Layer w15: v1(380.8,420.04) L4.2@380.8,458.73 ; L3.2@380.8,1604.98 v1(381.26,1662.24) ; v1(1323.5,4989.06) C78.1@1373,4989.06
  Bottom Layer w15: L510.1@536.63,1647.03 v1(573.32,1647.03)
  Bottom Layer w23.62: C546.1@586.51,3254.56 v1(615.89,3254.56)
  other v1: 1001.84,4664 1001.84,4698.42 1001.84,4732.84 1001.84,4767.26
-5VA_C: C502.1 C503.1 C542.1 C550.1 L510.2 U500.4 U501.4 U503.4 U504.2 U505.4 | length 96.1
  Bottom Layer w12: U504.2@665.16,3254.91 v1(699.61,3254.91)
  Bottom Layer w15: v1(2687.14,1297.34) C503.1@2687.14,1328.15 ; v1(2687.14,2443.59) C502.1@2687.14,2474.41
  other v1: 562.6,221.18 592,221.18 2687.14,1261.75 437.39,1553.34 472.52,1553.34 2673.49,2509.64 2700.51,2509.64
-5VA_OPA140_1: C4.2 C10.2 L3.1 U1.4
-5VA_OPA140_2: C3.2 C9.2 L4.1 U2.4
ADBUS6: J7.17 U18.23 | length 1304.2
  Top Layer w9: U18.23@2076.26,4130.44 v1(2076.26,4190.4)
  Signal 1 w9: v1(2076.26,4190.4) 2103.98,4218.12 2274.78,4218.12 2634.02,4577.35 2634.02,4627.4 2611.67,4649.74 2236.73,4649.74 J7.17@2187.48,4699
ADBUS7: J7.18 U18.24 | length 531.5
  Top Layer w9: v1(2046.1,4184.22) 2056.57,4173.74 U18.24@2056.57,4130.44
  Bottom Layer w9: v1(2046.1,4184.22) 2046.1,4457.62 J7.18@2187.48,4599
BDBUS4: J7.2 U18.30 | length 1355.3
  Top Layer w9: v1@1938.46,4082.93 v1(1938.46,4084.18) U18.30@1938.46,4130.44
  Signal 1 w9: v1(1938.46,4084.18) 1970.74,4051.91 2154.81,4051.91 2179.84,4076.95 2231.11,4076.95 2253.85,4054.21 2343.35,4054.21 2754.01,4464.87 2853.34,4464.87 J7.2@2987.48,4599
BDBUS5: J7.4 U18.32 | length 1249.2
  Top Layer w15: v1(1872.17,4130.44) U18.32@1896.58,4130.44
  Signal 1 w9.84: v1(1872.17,4130.44) 1890.76,4111.85 2376.36,4111.85 2749.31,4484.81 2773.28,4484.81 J7.4@2887.48,4599
BDBUS6: J7.6 U18.33 | length 1256.2
  Top Layer w9: v1(1828.36,4087.81) 1828.36,4060.95 1828.75,4060.56 U18.33@1829.21,4060.56
  Signal 1 w9.84: v1(1828.36,4087.81) 1828.36,4119.04 1862.68,4153.36 1897.2,4153.36 1914.64,4135.92 2366.67,4135.92 2787.48,4556.73 J7.6@2787.48,4599
BDBUS7: J7.8 U18.34 | length 1254.2
  Top Layer w9: v1(1783.9,4040.87) U18.34@1829.21,4040.87
  Signal 1 w9.84: v1(1783.9,4040.87) 1795.13,4052.11 1795.13,4111.05 1855.45,4171.37 1918.78,4171.37 1934.16,4155.99 2290.29,4155.99 2687.48,4553.18 J7.8@2687.48,4599
CDBUS4: J7.10 U18.43 | length 1368.5
  Top Layer w9: v1(1772.2,3863.71) U18.43@1829.21,3863.71
  Signal 1 w9: v1(1772.2,3863.71) 1813.43,3904.95 1813.43,3966.27 1758.23,4021.47 1758.23,4047.03 1776.5,4065.29 1776.5,4068.12 1777.01,4068.63 1777.01,4117.56 1848.24,4188.79 1908.37,4188.79 2004.22,4284.64 2273.11,4284.64 J7.10@2587.48,4599
CDBUS5: J7.12 U18.44 | length 1453.7
  Top Layer w9: U18.44@1829.21,3844.02 v1(1875.47,3844.02)
  Signal 1 w9: v1(1875.47,3844.02) 1872.5,3844.02 1865.33,3836.86 1738.94,3836.86 1711.35,3864.45 1711.35,4024.19 1762.01,4074.85 1762.01,4126.61 1851.64,4216.24 1897.02,4216.24 1998.89,4318.11 2248.64,4318.11 2487.48,4556.95 J7.12@2487.48,4599
CDBUS6: J7.14 U18.45 | length 1380.6
  Top Layer w9: v1(1773.87,3811.56) 1786.64,3824.34 U18.45@1829.21,3824.34
  Signal 1 w9.5: v1(1773.87,3811.56) 1731.37,3811.56 1688.76,3854.18 1688.76,3973.99 1673.22,3989.52 1673.22,4175.14 1747.33,4249.25 1835.92,4249.25 1934.7,4348.03 2108.21,4348.03 2349.78,4589.61 2378.08,4589.61 J7.14@2387.48,4599
CDBUS7: J7.16 U18.46 | length 1447
  Top Layer w9: U18.46@1829.21,3804.65 v1(1876.72,3804.65)
  Signal 1 w9.84: v1(1876.72,3804.65) 1811.69,3804.65 1795.67,3788.64 1719.04,3788.64 1670.36,3837.32 1670.36,3947.22 1649.81,3967.76 1649.81,4186.62 1758.11,4294.92 1851.32,4294.92 1928.66,4372.26 2025.4,4372.26 2246.24,4593.11 2281.58,4593.11 J7.16@2287.48,4599
CH1_ACDC_GAINADJ: R10.2 R548.1 U507.1 | length 2766.5
  Top Layer w9: R10.2@222.49,1897.02 239.44,1913.97 v1(239.44,1936.87)
  Bottom Layer w9: U507.1@223.11,2653.14 R548.1@223.11,2576.82 223.11,2400.69 192.99,2370.57 100.26,2370.57 72.72,2398.12 72.72,2548.7 -14.86,2636.27 -149.77,2636.27 -191.12,2594.93 -191.12,2464.12 -35.89,2308.89 -35.89,1959.76 -13.01,1936.87 59.56,1936.87 65.78,1943.1 65.78,2055.65 72.01,2061.87 101.06,2061.87 107.28,2055.65 107.28,1758.1 113.51,1751.87 142.56,1751.87 148.78,1758.1 148.78,2055.65 155.01,2061.87 184.06,2061.87 190.28,2055.65 190.28,1943.1 196.51,1936.87 v1(239.44,1936.87)
CH1_CALIB: C526.1 J3.2 R523.2 | length 1243.3
  Bottom Layer w9: J3.2@-134.53,1544.06 -35,1544.06 244.91,1264.16 416.64,1264.16 460.45,1307.97 718.08,1307.97 R523.2@860.28,1450.17 C526.1@915.79,1450.17
CH1_HYSIS: R154.2 R555.2 U507.4 | length 5455.2
  Top Layer w9: v1(272.05,2713.67) 291.72,2733.34 423.4,2733.34 544.12,2612.63 734.89,2612.63 782.72,2660.46 2702.72,2660.46 3147.44,3105.18 3477.56,3105.18 3549.53,3033.2 3549.53,2153.62 3440.55,2044.63 3196.15,2044.63 3125.91,2114.88 R154.2@3125.91,2480.19
  Bottom Layer w9: R555.2@135.78,2729.91 U507.4@223.11,2729.91 255.81,2729.91 v1(272.05,2713.67)
CH1_LMH6518_A+: R56.1 R58.2 R60.2 R144.1 | length 2103.6
  Top Layer w9: R58.2@952.9,2301.02 R56.1@952.9,2366.82 R60.2@1015.31,2366.82 1042.08,2366.82 ccw(c1042.08,2430.41) 1087.04,2385.44 1294.42,2592.82 cw(c1365.13,2522.11) 1365.13,2622.11 R144.1@2892,2622.11
CH1_LMH6518_A-: R48.2 R51.1 R53.2 | length 131.7
  Top Layer w9: R48.2@827.59,2366.82 R51.1@889.99,2366.82 cw(c858.05,2334.88) 903.22,2334.88 R53.2@903.22,2301.02
CH1_LMH6518_AVCM: C44.1 C48.1 R72.1 R515.2 U7.16 | length 40.8
  Bottom Layer w15: v1(1087.21,2253.01) R515.2@1128.05,2253.01
CH1_LMH6518_M+: R120.1 R121.1 U7.15 | length 134.2
  Top Layer w9.5: U7.15@983.18,2110.78 1000.49,2110.78 ccw(c1000.49,2138) 1019.73,2118.75
  Top Layer w20: 1019.73,2118.75 cw(c1056.73,2081.75) R120.1@1061.13,2133.89 ; R120.1@1061.38,2135 R121.1@1061.38,2185
CH1_LMH6518_M-: R118.1 R119.1 U7.14 | length 134.2
  Top Layer w9.5: U7.14@983.18,2091.1 1000.49,2091.1 cw(c1000.49,2063.88) 1019.73,2083.13
  Top Layer w20: 1019.73,2083.13 ccw(c1056.73,2120.13) R119.1@1061.13,2067.99 ; R118.1@1061.38,2015 R119.1@1061.38,2065
CH1_LMH6518_MVCM: C45.1 C49.1 R73.1 R516.2 U7.13 | length 38.7
  Bottom Layer w15: v1(1089.37,1948.87) R516.2@1128.05,1948.87
CH1_OFFSET: C564.1 R32.2 R541.2 | length 624.8
  Top Layer w9: v1(395,1304) 451.15,1304 660.73,1513.58 R32.2@660.73,1682.66
  Bottom Layer w9: C564.1@291.91,1304.22 R541.2@347.43,1304.22 347.64,1304 v1(395,1304)
CH1_TRIG_REF: C500.1 R143.1 R500.2 | length 157.3
  Top Layer w9: v1(2836.56,2529.96) 2859.22,2529.96 R143.1@2892,2562.74
  Bottom Layer w9: R500.2@2781.05,2562.71 C500.1@2836.56,2562.71 v1(2836.56,2529.96)
CH2_ACDC_GAINADJ: R9.2 R508.1 U502.1 | length 2775.1
  Top Layer w9: R9.2@222.49,750.77 239.44,767.72 v1(239.44,790.62)
  Bottom Layer w9: v1(239.44,790.62) 239.44,883.2 352.25,996.01 562.01,996.01 575.53,996.01 731.22,1151.71 731.22,1165.23 731.22,1288.08 831.71,1388.56 949.81,1388.56 1327.58,1766.33 1327.58,2703.47 R508.1@1390.1,2765.99 U502.1@1390.1,2842.3
CH2_CALIB: C523.1 J4.2 R518.2 | length 1352.4
  Top Layer w9: J4.2@-134.53,397.81 -87.72,351 174.3,351 450.13,75.18 v1(992.1,75.18)
  Bottom Layer w9: v1(992.1,75.18) R518.2@992.1,111.86 C523.1@1047.55,111.86
CH2_HYSIS: R155.2 R511.2 U502.4 | length 4790.5
  Top Layer w9: v1(3125.91,1299.19) R155.2@3125.91,1333.94
  Bottom Layer w9: 1251.25,2917.72 1251.25,3156.65 1306.75,3212.15 2539.27,3212.15 2831.3,2920.12 3497.08,2920.12 3520.53,2896.68 3626.44,2790.77 3626.44,1631.91 3383.44,1388.91 3215.62,1388.91 v1(3125.91,1299.19) ; R511.2@1298.91,2908.69 1303.61,2913.39 1316.96,2913.39 1322.64,2919.07 U502.4@1390.1,2919.07
  Bottom Layer w9.5: 1251.25,2917.72 1260.28,2908.69 R511.2@1298.91,2908.69
CH2_LMH6518_A+: R57.1 R59.2 R61.2 R146.1 | length 2231.8
  Top Layer w9: R146.1@2892,1475.86 1365.13,1475.86 ccw(c1365.13,1375.86) 1294.42,1446.57 1087.04,1239.19 cw(c1042.08,1284.15) 1042.08,1220.57 R61.2@1015.31,1220.57 ; R57.1@952.91,1220.57 952.9,1154.76 R57.1@952.91,1220.57 ; R57.1@952.91,1220.57 R61.2@1015.31,1220.57 ; R57.1@952.91,1220.57 R61.2@1015.31,1220.57
CH2_LMH6518_A-: R49.2 R52.1 R54.2 | length 131.7
  Top Layer w9: R49.2@827.59,1220.57 R52.1@889.99,1220.57 cw(c858.05,1188.63) 903.22,1188.63 R54.2@903.22,1154.76
CH2_LMH6518_AVCM: C46.1 C50.1 R74.1 R513.2 U8.16 | length 42.5
  Bottom Layer w15: v1(1091.29,1090.45) 1110.76,1090.45 R513.2@1127.07,1106.76
CH2_LMH6518_M+: R124.1 R125.1 U8.15 | length 129.8
  Top Layer w9.5: U8.15@983.18,964.53 1000.49,964.53 ccw(c1000.49,991.74) 1019.73,972.5
  Top Layer w20: 1019.73,972.5 cw(c1056.73,935.5) R124.1@1056.73,987.82 ; R124.1@1061.38,990 R125.1@1061.38,1040
CH2_LMH6518_M-: R122.1 R123.1 U8.14 | length 129.8
  Top Layer w9.84: U8.14@983.18,944.84 1000.49,944.84 cw(c1000.49,917.63) 1019.73,936.87
  Top Layer w20: 1019.73,936.87 ccw(c1056.73,973.87) R123.1@1056.73,921.55 ; R122.1@1061.38,870 R123.1@1061.38,920
CH2_LMH6518_MVCM: C47.1 C51.1 R75.1 R514.2 U8.13 | length 38.7
  Bottom Layer w15: v1(1089.37,802.61) R514.2@1128.05,802.61
CH2_OFFSET: C557.1 R33.2 R535.2 | length 1587.6
  Top Layer w9: v1(660.73,505.68) R33.2@660.73,536.41
  Bottom Layer w9: 424.36,-40.7 427.27,-37.78 R535.2@459.51,-37.78 979.17,-37.78 1092.46,75.51 1092.46,433.71 1020.49,505.68 v1(660.73,505.68)
  Bottom Layer w10: C557.1@403.4,-40.74 424.36,-40.7
CH2_TRIG_REF: C501.1 R145.1 R501.2 | length 160.1
  Top Layer w9: v1(2892,1381.74) R145.1@2892,1416.49
  Bottom Layer w9: R501.2@2781.04,1416.45 C501.1@2836.55,1416.45 2857.28,1416.46 v1(2892,1381.74)
CLH_1: R543.2 R545.1 U3.15 | length 224.2
  Top Layer w9: U3.15@376.08,2136.45 v1(376.08,2245.92)
  Bottom Layer w9: R543.2@317.2,2212.12 R545.1@317.19,2261.5 360.51,2261.49 v1(376.08,2245.92)
CLH_2: R544.2 R546.1 U4.15 | length 237.8
  Top Layer w9: v1@376,1093 376.08,1092.92 U4.15@376.08,990.2
  Bottom Layer w9: R546.1@316.94,1129.68 R544.2@317.2,1065.87 ; R546.1@317.16,1128.06 346.4,1128.06 v1(376.01,1098.45)
CLL_1: R24.1 R536.2 U3.14 | length 191.7
  Top Layer w9: U3.14@395.85,2136.37 395.85,2167.59 cw(c454.41,2167.59) 413,2209 cw(c420.53,2201.47) 420.53,2212.12 v1(462.16,2212.12) R24.1@497.86,2212.12
  Bottom Layer w9: R536.2@433.35,2212.12 v1(462.16,2212.12)
CLL_2: R25.1 R537.2 U4.14 | length 191.9
  Top Layer w9: U4.14@395.85,990.12 395.85,1021.59 cw(c454.41,1021.59) 413,1063 cw(c419.92,1056.08) 419.92,1065.87 v1(462.16,1065.87) R25.1@497.86,1065.87
  Bottom Layer w9: R537.2@433.35,1065.87 v1(462.16,1065.87)
DAC_CH0: R502.2 U24.2 | length 2597.6
  Signal 1 w9: v1(265.57,1553.72) 317.91,1501.38 675.63,1501.38 725.6,1551.35 725.6,2160.72 657.67,2228.65 657.67,2347.79 378.51,2626.95 378.51,3327.89 v1(407.38,3356.76)
  Bottom Layer w9: R502.2@246.98,1606.22 246.98,1572.3 v1(265.57,1553.72) ; v1(407.38,3356.76) 445.36,3394.74 U24.2@445.36,3414.88
DAC_CH1: U24.3 U505.5 | length 2249.8
  Signal 1 w9: v1(363.51,3366.63) 363.51,3364.34 355.03,3355.86 355.03,2618.16 608.87,2364.33 608.87,2183.59 499.84,2074.56 499.84,1685.53 631.81,1553.56 v1(695.99,1553.56)
  Bottom Layer w9: v1(363.51,3366.63) 379.38,3382.49 407.83,3382.49 425.67,3400.33 U24.3@425.67,3414.88 ; U505.5@649,1520.86 685.17,1520.86 695.99,1531.68 v1(695.99,1553.56)
DAC_CH2: R504.2 U24.4 | length 3403.3
  Signal 1 w9: v1(354.14,3404.65) 308.6,3359.12 308.6,2384.97 224.23,2300.6 224.23,2254.5 205.29,2235.56 205.29,1391.89 216.94,1380.24 216.94,381.52 v1(370.06,228.4)
  Bottom Layer w9: v1(354.14,3404.65) 358.2,3404.65 368.42,3414.88 U24.4@405.99,3414.88 ; v1(370.06,228.4) R504.2@411.16,228.4
DAC_CH3: U24.5 U503.5 | length 4008.4
  Signal 1 w9: v1(352.86,3440.47) 280.12,3440.47 232.84,3393.19 232.84,2939.04 197.1,2903.3 197.1,2690.89 166.44,2660.23 166.44,1722.71 150.59,1706.86 150.59,1135.17 187.43,1098.33 187.43,326.71 323.75,190.4 v1(807,190.4)
  Bottom Layer w9: v1(352.86,3440.47) U24.5@380.39,3440.47 ; U503.5@760.83,182.55 799.15,182.55 v1(807,190.4)
DAC_CH4: U24.8 U500.3 | length 3518.2
  Signal 1 w9: v1(338.43,3540.26) 338.43,3573.91 381.45,3616.93 422.76,3616.93 436.46,3603.23 436.46,3529.44 473.4,3492.49 473.4,2890.42 438.26,2855.28 438.26,2802.17 606.64,2633.79 2661.53,2633.79 v1(2739.03,2556.29)
  Bottom Layer w9: v1(338.43,3540.26) 338.43,3521.09 360,3499.52 U24.8@380.39,3499.52 ; U500.3@2687.14,2574.52 2720.8,2574.52 v1(2739.03,2556.29)
DAC_CH5: U24.9 U501.3 | length 4273.5
  Signal 1 w9: v1(394.23,3553.75) 394.23,3401.73 429.88,3366.08 429.88,3067.59 417.64,3055.35 417.64,2744.93 653.58,2508.98 1195.08,2508.98 1230.86,2473.21 2504.88,2473.21 2736.08,2242.01 v1(2736.08,1412.76)
  Bottom Layer w9: v1(394.23,3553.75) 405.99,3541.99 U24.9@405.99,3525.11 ; U501.3@2687.13,1428.27 2720.57,1428.27 v1(2736.08,1412.76)
DAC_CS0: U9.12 U24.12 | length 815.7
  Top Layer w10: U9.12@961.56,3948.63 v1(1007.07,3948.63)
  Signal 1 w9: v1(478.27,3553.75) 478.27,3628.33 798.58,3948.63 v1(1007.07,3948.63)
  Bottom Layer w9: U24.12@465.04,3525.11 465.04,3540.52 v1(478.27,3553.75)
DAC_SCLK: U9.4 U24.13 | length 898
  Top Layer w10: v1(1148.34,3923.04) U9.4@1193.85,3923.04
  Signal 1 w9: v1(512.97,3545.32) 779.68,3545.32 1146.24,3911.88 1146.24,3920.94 v1(1148.34,3923.04)
  Bottom Layer w9: U24.13@490.63,3499.52 490.63,3524 v1(512.97,3545.32)
DAC_SDI: U9.7 U24.14 | length 1086.1
  Top Layer w10: U9.7@1193.85,3999.81 v1(1239.35,3999.81)
  Signal 1 w9: v1(527.47,3505.38) 551.58,3481.28 794.33,3481.28 1194.7,3881.65 1194.7,3978.2 1216.31,3999.81 v1(1239.35,3999.81)
  Bottom Layer w9: U24.14@490.72,3479.92 502.3,3479.92 v1@527.62,3505.24
DAC_SDO_ALARM: U9.9 U24.15 | length 1033.8
  Top Layer w10: v1(916.06,4025.4) U9.9@961.56,4025.4
  Signal 1 w9: v1(530.59,3467.13) 453.46,3544.26 453.46,3842.05 636.82,4025.4 v1(916.06,4025.4)
  Bottom Layer w9: U24.15@490.63,3460.15 508.64,3460.15 515.62,3467.13 v1(530.59,3467.13)
DDBUS7: J7.15 U18.59 | length 2357.1
  Top Layer w9: U18.59@2095.94,3695.4 2095.94,3734.64 v1(2109.64,3748.34)
  Signal 1 w9: v1(2109.64,3748.34) 2109.64,3814.79 2187.25,3892.4 2249.73,3892.4 2552.37,4195.05 2552.88,4195.05 2784.33,4426.51 2885.64,4426.51 3089.27,4630.15 3089.27,4697.92 3034.31,4752.88 2341.36,4752.88 J7.15@2287.48,4699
